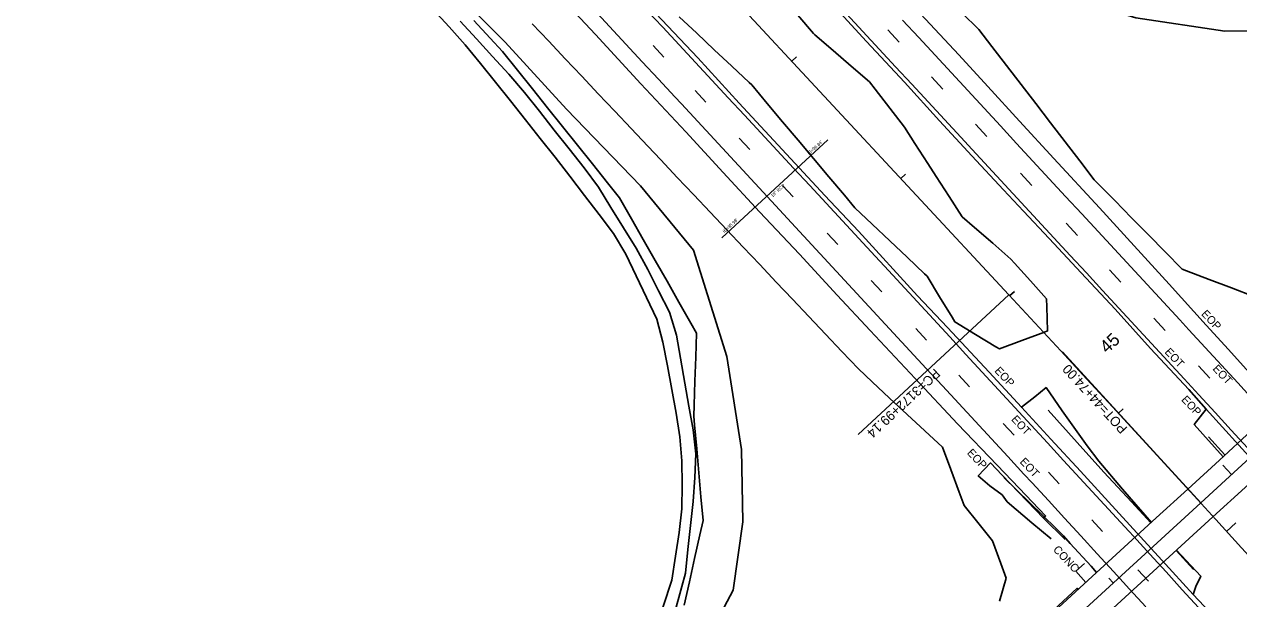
# Model space of a CAD drawing. Extents: x 2132221 to 2141942, y 535736 to 547298.
# Drawn here: x 2135355 to 2136113, y 543005 to 543363 of the extents above; entities that cross this region are included whole.
import ezdxf

# ---------------------------------------------------------------- set-up
doc = ezdxf.new("R2010")
doc.units = 0
for name, color, linetype in [('RD_EX_Bridge', 7, 'Continuous'), ('RD_EX_Conc', 7, 'Continuous'), ('RD_EX_Conc_txCode', 7, 'Continuous'), ('RD_EX_DR_Inlet_txCode', 7, 'Continuous'), ('RD_EX_DR_Pipe', 7, 'Continuous'), ('RD_EX_DR_Pipe_txCode', 7, 'Continuous'), ('RD_EX_Driveway', 7, 'Continuous'), ('RD_EX_Fence_Other', 7, 'Continuous'), ('RD_EX_GuardRail', 7, 'Continuous'), ('RD_EX_Misc', 7, 'Continuous'), ('RD_EX_Misc_txCode', 7, 'Continuous'), ('RD_EX_Road', 7, 'Continuous'), ('RD_EX_Road_txCode', 7, 'Continuous'), ('RD_EX_VEG', 7, 'Continuous'), ('RD_HC_Cl', 7, 'Continuous'), ('RD_HC_Data', 7, 'Continuous'), ('RD_HC_Data_Tic', 7, 'Continuous'), ('RD_HC_TX_Sta50', 7, 'Continuous')]:
    doc.layers.add(name, color=color, linetype=linetype)

msp = doc.modelspace()

# ---------------------------------------------------------------- linework, layer by layer
at = {"layer": 'RD_EX_Bridge'}
msp.add_lwpolyline([(2136193.68, 543144.07), (2136175.22, 543127.4), (2136156.9, 543110.48), (2136137.15, 543092.41), (2136117.1, 543074.1), (2136097.08, 543055.86), (2136077.3, 543037.76), (2136057.22, 543019.33), (2136037.23, 543001.11), (2136019.11, 542984.53), (2136000.71, 542967.64), (2135984.78, 542984.82), (2136003.22, 543001.71), (2136021.59, 543018.53), (2136041.56, 543036.86), (2136061.61, 543055.13), (2136081.34, 543073.08), (2136101.12, 543091.33), (2136121.02, 543109.6), (2136141.1, 543127.98), (2136159.66, 543144.89), (2136177.9, 543161.59)], close=True, dxfattribs=at)
at = {"layer": 'RD_EX_Conc'}
for points in [[(2136017.57, 543014.85), (2136011.5, 543021.9), (2136016.77, 543026.64)], [(2135986.29, 542986.21), (2135985.82, 542986.73), (2136012.19, 543011.24), (2136012.85, 543010.53)]]:
    msp.add_lwpolyline(points, dxfattribs=at)
at = {"layer": 'RD_EX_DR_Pipe'}
msp.add_lwpolyline([(2135856.59, 543291.22), (2135790.19, 543230.11)], dxfattribs=at)
at = {"layer": 'RD_EX_Driveway'}
for points in [[(2135759.15, 543016.37), (2135761.39, 543031.2), (2135763.64, 543046.03), (2135765.25, 543060.92), (2135765.6, 543075.91), (2135765.21, 543090.89), (2135763.98, 543105.84), (2135761.85, 543120.66), (2135759.05, 543135.4), (2135756.25, 543150.14), (2135753.45, 543164.87), (2135749.65, 543179.28), (2135743.18, 543192.81), (2135736.71, 543206.34), (2135730.24, 543219.88), (2135722.68, 543232.75), (2135713.59, 543244.67), (2135704.49, 543256.6), (2135695.39, 543268.53), (2135686.25, 543280.42), (2135676.9, 543292.15), (2135667.56, 543303.88), (2135658.21, 543315.62), (2135648.86, 543327.35), (2135639.52, 543339.08), (2135630.06, 543350.72), (2135619.94, 543361.79), (2135609.83, 543372.87)], [(2135626.77, 543365.43), (2135636.95, 543354.42), (2135647.13, 543343.4), (2135657.31, 543332.39), (2135667, 543320.94), (2135676.3, 543309.17), (2135685.6, 543297.4), (2135694.9, 543285.63), (2135704.2, 543273.86), (2135713.15, 543261.83), (2135721.05, 543249.08), (2135728.95, 543236.32), (2135736.84, 543223.57), (2135744.01, 543210.39), (2135750.77, 543197), (2135757.53, 543183.61), (2135761.93, 543169.27), (2135769.75, 543124.96), (2135772.35, 543110.19), (2135774.09, 543095.29), (2135773.41, 543080.31), (2135772.29, 543065.35), (2135770.7, 543050.43), (2135769.1, 543035.52), (2135767.51, 543020.61), (2135765.28, 543012.23)]]:
    msp.add_lwpolyline(points, dxfattribs=at)
at = {"layer": 'RD_EX_Fence_Other'}
for points in [[(2135823.93, 542885.7), (2135795.33, 542914.04), (2135763.79, 542946.84), (2135797.37, 543010.14), (2135803.38, 543052.63), (2135802.52, 543097.85), (2135793.36, 543156.09), (2135772.59, 543222.35), (2135739.5, 543262.57), (2135693.33, 543310.54), (2135654.86, 543352.42), (2135615, 543392.72), (2135572.08, 543440.01), (2135537.94, 543477.76), (2135489.32, 543528.57), (2135449.53, 543571.95), (2135407.25, 543616.47), (2135366.86, 543659.37)], [(2135995.12, 543384.2), (2136048.83, 543367.47), (2136104.6, 543359.2), (2136149.03, 543359.37), (2136192.31, 543366.7), (2136251.44, 543270.66)]]:
    msp.add_lwpolyline(points, dxfattribs=at)
at = {"layer": 'RD_EX_GuardRail'}
for points in [[(2136058.24, 543052.06), (2136046.24, 543065.16), (2136028.9, 543083.69), (2136012.23, 543102.34), (2135994.17, 543122.53)], [(2136094.31, 543105.79), (2136104.56, 543094.49)], [(2135966.44, 543080.44), (2135990.51, 543056.97), (2135999.06, 543048.51), (2136003.62, 543043.92), (2136007.9, 543039.24), (2136021, 543024.95), (2136024.43, 543021.14)], [(2136084.97, 543022.88), (2136074.06, 543034.78)]]:
    msp.add_lwpolyline(points, dxfattribs=at)
at = {"layer": 'RD_EX_Misc'}
for p, q in [((2135894.01, 543359.98), (2135901.11, 543352.29)), ((2135747.36, 543350.29), (2135754.06, 543343.04)), ((2135921.19, 543330.63), (2135928.29, 543322.94)), ((2135773.65, 543322.15), (2135780.35, 543314.9)), ((2135948.71, 543301.07), (2135955.81, 543293.38)), ((2135801.06, 543292.42), (2135807.76, 543285.18)), ((2135976.79, 543270.49), (2135983.89, 543262.81)), ((2135828.24, 543262.89), (2135834.94, 543255.65)), ((2136005.46, 543239.29), (2136012.56, 543231.61)), ((2135856.02, 543233.12), (2135862.72, 543225.88)), ((2136032.42, 543210.12), (2136039.52, 543202.44)), ((2135883.56, 543203.53), (2135890.26, 543196.29)), ((2136060.19, 543179.97), (2136067.29, 543172.29)), ((2135911.4, 543173.47), (2135918.1, 543166.22)), ((2136088.05, 543150.12), (2136095.16, 543142.43)), ((2135938.28, 543144.36), (2135944.98, 543137.11)), ((2135966.13, 543114.2), (2135972.84, 543106.95)), ((2135994.33, 543083.65), (2136001.04, 543076.4)), ((2136021.34, 543053.91), (2136028.04, 543046.66)), ((2136050.05, 543022.84), (2136056.75, 543015.6))]:
    msp.add_line(p, q, dxfattribs=at)
for points in [[(2135709.98, 543373.09), (2135720.19, 543362.09), (2135730.4, 543351.1), (2135740.6, 543340.11), (2135750.81, 543329.12), (2135761.01, 543318.13), (2135765.09, 543313.73), (2135775.28, 543302.72), (2135785.47, 543291.71), (2135795.66, 543280.7), (2135805.85, 543269.69), (2135816.03, 543258.68), (2135826.22, 543247.68), (2135836.41, 543236.67), (2135846.6, 543225.66), (2135856.78, 543214.65), (2135866.97, 543203.64), (2135877.16, 543192.63), (2135887.35, 543181.62), (2135897.54, 543170.61), (2135907.72, 543159.6), (2135917.91, 543148.59), (2135928.1, 543137.58), (2135938.29, 543126.57), (2135948.48, 543115.56), (2135958.66, 543104.55), (2135968.85, 543093.54), (2135979.04, 543082.53), (2135984.12, 543077.04), (2135994.27, 543065.99), (2136004.41, 543054.94), (2136014.56, 543043.89), (2136024.7, 543032.84), (2136034.85, 543021.79), (2136044.99, 543010.74), (2136055.14, 542999.69)], [(2135743.13, 543372.58), (2135753.34, 543361.59), (2135763.55, 543350.6), (2135773.76, 543339.61), (2135783.97, 543328.63), (2135794.18, 543317.64), (2135804.39, 543306.65), (2135814.6, 543295.66), (2135824.81, 543284.67), (2135835.03, 543273.69), (2135845.24, 543262.7), (2135855.45, 543251.71), (2135865.66, 543240.72), (2135875.87, 543229.73), (2135886.08, 543218.74), (2135891.96, 543212.41), (2135902.13, 543201.39), (2135912.3, 543190.36), (2135922.46, 543179.33), (2135932.63, 543168.3), (2135942.8, 543157.27), (2135952.97, 543146.24), (2135963.13, 543135.22), (2135973.3, 543124.19), (2135983.47, 543113.16), (2135993.64, 543102.13), (2136003.8, 543091.1), (2136013.97, 543080.07), (2136024.14, 543069.05), (2136034.31, 543058.02), (2136044.47, 543046.99), (2136047.59, 543043.61), (2136057.69, 543032.51), (2136067.78, 543021.41), (2136077.87, 543010.32), (2136087.97, 542999.22)], [(2135868.09, 543369.95), (2135878.3, 543358.96), (2135888.5, 543347.97), (2135898.71, 543336.98), (2135908.91, 543325.99), (2135919.12, 543314.99), (2135929.33, 543304), (2135939.53, 543293.01), (2135946.73, 543285.25), (2135956.91, 543274.24), (2135967.1, 543263.22), (2135977.28, 543252.21), (2135987.46, 543241.19), (2135997.64, 543230.18), (2136007.82, 543219.16), (2136018, 543208.15), (2136028.18, 543197.13), (2136038.37, 543186.12), (2136048.55, 543175.1), (2136058.73, 543164.09), (2136068.91, 543153.07), (2136079.09, 543142.06), (2136088.3, 543132.09), (2136098.42, 543121.01), (2136108.53, 543109.93), (2136118.64, 543098.86)], [(2135903.17, 543366.14), (2135913.35, 543355.13), (2135923.53, 543344.12), (2135933.72, 543333.1), (2135943.9, 543322.09), (2135954.09, 543311.08), (2135964.27, 543300.06), (2135974.45, 543289.05), (2135984.64, 543278.04), (2135994.82, 543267.02), (2136005, 543256.01), (2136015.19, 543245), (2136025.37, 543233.98), (2136035.56, 543222.97), (2136045.74, 543211.96), (2136055.92, 543200.95), (2136066.11, 543189.93), (2136076.29, 543178.92), (2136082.06, 543172.68), (2136092.22, 543161.64), (2136102.38, 543150.6), (2136112.54, 543139.57), (2136122.7, 543128.53)]]:
    msp.add_lwpolyline(points, dxfattribs=at)
at = {"layer": 'RD_EX_Road'}
msp.add_line((2135991.21, 543055.06), (2136004.69, 543041.79), dxfattribs=at)
for points in [[(2136139.92, 543126.9), (2136132.97, 543134.79), (2136126.46, 543141.43), (2136119.61, 543145.97), (2136106.75, 543160.44), (2136092.87, 543175.54), (2136069.64, 543201.25), (2136047.83, 543225.01), (2136026.13, 543248.75), (2135997.77, 543279.74), (2135976.21, 543302.94), (2135956.47, 543324.6), (2135938.3, 543344.31), (2135914.49, 543369.99), (2135894.88, 543391.11), (2135878.91, 543408.82), (2135859.8, 543429.43), (2135841.19, 543449.24), (2135822.8, 543469.03), (2135809.12, 543483.98), (2135792.45, 543501.64), (2135773.96, 543521.48), (2135757.73, 543538.48), (2135742.49, 543554.63)], [(2135714.4, 543531.47), (2135737.39, 543506.64), (2135759.54, 543482.81), (2135781.42, 543459.43), (2135808.13, 543430.68), (2135834.82, 543402.2), (2135857.16, 543378.37), (2135880.71, 543352.77), (2135904.34, 543327.39), (2135926.33, 543303.14), (2135946.42, 543281.25), (2135966.31, 543260.17), (2135978.72, 543246.68), (2135994.71, 543229.64), (2136014.74, 543208.26), (2136035.93, 543185.45), (2136058.04, 543160.98), (2136082.07, 543135.32), (2136092.92, 543123.13), (2136085.37, 543113.61), (2136103.4, 543093.42)], [(2135650.42, 543476.39), (2135672.83, 543452.46), (2135694.05, 543429.77), (2135715.14, 543406.82), (2135745.4, 543374.16), (2135775.28, 543342.6), (2135801.16, 543314.24), (2135827.89, 543285.27), (2135854.67, 543256.49), (2135875.64, 543234.32), (2135912.61, 543193.94), (2135931.36, 543174.08), (2135957.2, 543146.15), (2135977.44, 543124.31), (2135985.75, 543130.84), (2135992.83, 543136.58), (2136002.84, 543121.96), (2136018.49, 543100.1), (2136025.71, 543090.52), (2136040.63, 543073.22), (2136058.6, 543052.39)], [(2135689.02, 543381.05), (2135711.44, 543357.15), (2135739.8, 543326.3), (2135767.84, 543296.24), (2135791.18, 543270.96), (2135813.92, 543246.37), (2135838.91, 543219.89), (2135862.36, 543194.24), (2135883.02, 543172.25), (2135911.06, 543142.18), (2135937.59, 543113.92), (2135962.2, 543088.15), (2135975.97, 543073.75), (2135992.48, 543056.4), (2135992.48, 543056.4), (2135991.21, 543055.06), (2135965.51, 543081.81), (2135958.21, 543089.49), (2135950.46, 543081.38), (2135957.65, 543075.19), (2135965.32, 543069.5), (2135968.45, 543065.24), (2135983.99, 543052.04), (2135995.99, 543042.11)], [(2135977.44, 543124.31), (2135995.88, 543104.38), (2136014.27, 543084.45), (2136031.81, 543065.31), (2136071.87, 543021.53), (2136084.75, 543007.41)], [(2136092.92, 543123.13), (2136133.67, 543078.07), (2136155.38, 543053.88), (2136177.97, 543029.25), (2136200.32, 543005.2)], [(2136074.4, 543035.09), (2136089.46, 543018.7), (2136086.31, 543012.26), (2136084.75, 543007.41), (2136098.45, 542992.85), (2136117.96, 542971.03), (2136131.21, 542956.79), (2136152.96, 542932.59)], [(2135675.24, 542699.18), (2135675.35, 542712.86), (2135675.18, 542720.48), (2135675.26, 542729.73), (2135673.77, 542739.85), (2135672.62, 542751.79), (2135670.81, 542762.63), (2135668.86, 542771.75), (2135667.19, 542783.75), (2135666, 542797.62), (2135665.34, 542809.83), (2135666.36, 542818.28), (2135668.42, 542827.81), (2135670.48, 542835.85), (2135674.54, 542846.14), (2135678.34, 542852.63), (2135713.22, 542920.39), (2135720.87, 542933.13), (2135732.66, 542952.79), (2135740.07, 542967.18), (2135753.65, 542999.94), (2135759.15, 543016.37)], [(2135760.53, 542994.83), (2135765.28, 543012.23)]]:
    msp.add_lwpolyline(points, dxfattribs=at)
at = {"layer": 'RD_EX_VEG'}
for points in [[(2135763.73, 543368.17), (2135774.66, 543357.89), (2135785.59, 543347.61), (2135796.52, 543337.34), (2135807.44, 543327.06), (2135809, 543325.6), (2135818.64, 543314.11), (2135828.28, 543302.62), (2135837.93, 543291.13), (2135847.57, 543279.64), (2135857.21, 543268.15), (2135866.86, 543256.66), (2135873.37, 543248.91), (2135884.26, 543238.59), (2135895.15, 543228.28), (2135906.04, 543217.96), (2135916.93, 543207.65), (2135918.51, 543206.15), (2135926.29, 543193.33), (2135934.08, 543180.51), (2135935.87, 543177.56), (2135948.69, 543169.79), (2135961.52, 543162.01), (2135963.64, 543160.73), (2135977.7, 543165.95), (2135991.76, 543171.18), (2135993.83, 543171.95), (2135993.23, 543186.94), (2135993.02, 543191.99), (2135983.04, 543203.18), (2135973.05, 543214.38), (2135970.86, 543216.84), (2135959.53, 543226.68), (2135948.21, 543236.52), (2135940.41, 543243.3), (2135932.28, 543255.9), (2135924.15, 543268.51), (2135919.04, 543276.43), (2135910.91, 543289.04), (2135904.37, 543299.18), (2135895.18, 543311.04), (2135886, 543322.89), (2135882.45, 543327.47), (2135871.09, 543337.27), (2135859.74, 543347.07), (2135848.38, 543356.87), (2135847.46, 543357.67), (2135837.72, 543369.08)], [(2136122.67, 543193.47), (2136108.65, 543198.81), (2136094.63, 543204.16), (2136080.62, 543209.5), (2136077.79, 543210.57), (2136067.28, 543221.27), (2136056.77, 543231.97), (2136046.25, 543242.67), (2136035.74, 543253.37), (2136025.22, 543264.07), (2136022.97, 543266.36), (2136013.83, 543278.25), (2136004.69, 543290.14), (2135995.55, 543302.03), (2135986.4, 543313.92), (2135977.26, 543325.81), (2135968.12, 543337.71), (2135958.97, 543349.6), (2135950.86, 543360.15), (2135940.18, 543370.69)], [(2135635.35, 543365.77), (2135645.54, 543354.76), (2135653.19, 543346.49), (2135662.56, 543334.78), (2135671.94, 543323.07), (2135681.31, 543311.36), (2135690.69, 543299.66), (2135700.07, 543287.95), (2135709.44, 543276.24), (2135718.82, 543264.53), (2135726.37, 543255.1), (2135733.79, 543242.07), (2135741.21, 543229.03), (2135748.64, 543215.99), (2135756.06, 543202.96), (2135763.48, 543189.92), (2135770.9, 543176.89), (2135774.45, 543170.66), (2135773.97, 543155.67), (2135773.49, 543140.67), (2135773.02, 543125.68), (2135772.8, 543118.79)], [(2135928.05, 543099.36), (2135917.08, 543109.58), (2135906.1, 543119.8), (2135895.12, 543130.03), (2135884.15, 543140.25), (2135875.58, 543148.23), (2135865.27, 543159.13), (2135854.97, 543170.03), (2135844.66, 543180.93), (2135834.36, 543191.83), (2135824.3, 543202.48), (2135813.99, 543213.38), (2135803.69, 543224.28), (2135793.38, 543235.18), (2135783.08, 543246.08), (2135772.77, 543256.98), (2135762.47, 543267.88), (2135752.16, 543278.78), (2135743.97, 543287.45), (2135733.66, 543298.35), (2135723.36, 543309.25), (2135713.05, 543320.15), (2135702.75, 543331.05), (2135692.44, 543341.95), (2135682.14, 543352.85), (2135671.83, 543363.75)], [(2135766.81, 543000.59), (2135770.06, 543015.23), (2135773.31, 543029.88), (2135776.56, 543044.52), (2135778.55, 543053.46), (2135777.23, 543068.4), (2135775.92, 543083.35), (2135774.6, 543098.29), (2135773.29, 543113.23), (2135772.8, 543118.79)], [(2135928.05, 543099.36), (2135933.32, 543085.31), (2135938.58, 543071.26), (2135941.68, 543063.01), (2135951.01, 543051.27), (2135959.3, 543040.83), (2135964.48, 543026.76), (2135967.85, 543017.59), (2135963.75, 543003.16)]]:
    msp.add_lwpolyline(points, dxfattribs=at)
at = {"layer": 'RD_HC_Cl'}
for p, q in [((2132442.23, 546992.78), (2135969.5, 543194.56)), ((2136089.41, 543064.66), (2136458.11, 543402.38)), ((2135592.36, 542609.37), (2136089.41, 543064.66))]:
    msp.add_line(p, q, dxfattribs=at)
msp.add_arc((2118950.8, 527389.88), 23225.51, 39.112741, 42.881786, dxfattribs=at)
at = {"layer": 'RD_HC_Data'}
for p, q in [((2135969.5, 543194.56), (2135875.55, 543107.3)), ((2136089.41, 543064.66), (2136003.07, 543158.92))]:
    msp.add_line(p, q, dxfattribs=at)
at = {"layer": 'RD_HC_Data_Tic'}
for p, q in [((2135833.99, 543340.47), (2135836.92, 543343.2)), ((2135902.04, 543267.2), (2135904.97, 543269.92)), ((2135970.09, 543193.92), (2135973.02, 543196.64)), ((2136037.98, 543120.5), (2136040.92, 543123.21)), ((2136108.58, 543082.22), (2136103.17, 543088.11)), ((2136105.55, 543046.78), (2136111.46, 543052.18)), ((2136034.84, 543014.67), (2136032.14, 543017.62))]:
    msp.add_line(p, q, dxfattribs=at)

# ---------------------------------------------------------------- texts
at = {"layer": 'RD_EX_Conc_txCode'}
msp.add_text('CONC', height=5, rotation=313.25476, dxfattribs=at).set_placement((2135996.88, 543035.06))
at = {"layer": 'RD_EX_DR_Inlet_txCode'}
for s, p in [("IE=96.84'", (2135844.82, 543281.75)), ("IE=95.98'", (2135791.9, 543233.04))]:
    msp.add_text(s, height=2, rotation=42.62329, dxfattribs=at).set_placement(p)
at = {"layer": 'RD_EX_DR_Pipe_txCode'}
msp.add_text('18" RCP', height=2, rotation=42.62329, dxfattribs=at).set_placement((2135822.03, 543255.34))
at = {"layer": 'RD_EX_Misc_txCode'}
for p in [(2136066.59, 543158.54), (2136096.55, 543148.03), (2135970.77, 543116.44), (2135976.07, 543089.97)]:
    msp.add_text('EOT', height=5, rotation=313.25476, dxfattribs=at).set_placement(p)
at = {"layer": 'RD_EX_Road_txCode'}
for p in [(2136089.44, 543182.25), (2135960.31, 543146.77), (2136076.99, 543128.73), (2135943.11, 543095.51)]:
    msp.add_text('EOP', height=5, rotation=313.25476, dxfattribs=at).set_placement(p)
at = {"layer": 'RD_HC_Data'}
for s, rotation, p in [('PC=3172+99.14', 222.88179, (2135923.23, 543148.86)), ('POT=44+74.00', 132.48911, (2136044.03, 543111.24))]:
    msp.add_text(s, height=6, rotation=rotation, dxfattribs=at).set_placement(p)
at = {"layer": 'RD_HC_TX_Sta50'}
msp.add_text('45', height=8, rotation=42.48911, dxfattribs=at).set_placement((2136030.87, 543157.5))

doc.saveas('drawing.dxf')
